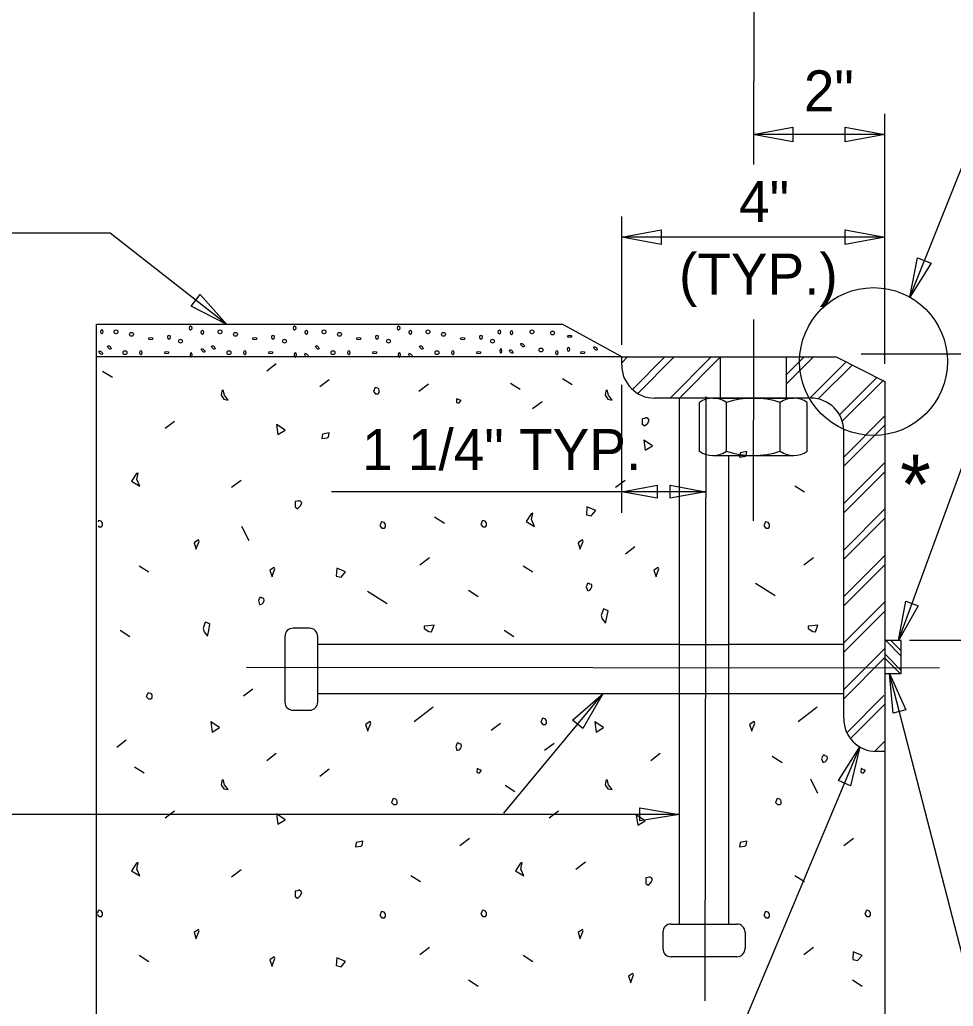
# Model space of a CAD drawing. Extents: x 0 to 11.3, y 0 to 7.9.
# Drawn here: x 1.652 to 2.835, y 1.767 to 3.018 of the extents above; entities that cross this region are included whole.
import ezdxf

# ---------------------------------------------------------------- set-up
doc = ezdxf.new("R2010")
doc.units = 0
for name, color, linetype in [('BRDG_ANNO_General-Notes', 7, 'Continuous'), ('BRDG_BASE_Dtlctrln', 7, 'Continuous'), ('BRDG_BASE_Hidden-Line', 7, 'Continuous'), ('BRDG_BASE_Obj-Line', 7, 'Continuous'), ('BRDG_BASE_Pattern', 7, 'Continuous')]:
    doc.layers.add(name, color=color, linetype=linetype)

msp = doc.modelspace()

# ---------------------------------------------------------------- linework, layer by layer
at = {"layer": 'BRDG_ANNO_General-Notes'}
for p, q in [((2.78, 2.6662), (2.9177, 3.0101)), ((2.7484, 2.5817), (2.7484, 2.8984)), ((2.5817, 2.8724), (2.6317, 2.8818)), ((2.6317, 2.8818), (2.6317, 2.863)), ((2.6984, 2.863), (2.6984, 2.8818)), ((2.6984, 2.8818), (2.7484, 2.8724)), ((2.7484, 2.8724), (2.5817, 2.8724)), ((2.6317, 2.863), (2.5817, 2.8724)), ((2.7484, 2.8724), (2.6984, 2.863)), ((2.4151, 2.6059), (2.4151, 2.7682)), ((2.4151, 2.7422), (2.4651, 2.7516)), ((2.4651, 2.7516), (2.4651, 2.7328)), ((2.6984, 2.7328), (2.6984, 2.7516)), ((2.6984, 2.7516), (2.7484, 2.7422)), ((1.7666, 2.7472), (0.6362, 2.7472)), ((1.9143, 2.6315), (1.7666, 2.7472)), ((2.7484, 2.7422), (2.4151, 2.7422)), ((2.4651, 2.7328), (2.4151, 2.7422)), ((2.7484, 2.7422), (2.6984, 2.7328)), ((2.78, 2.6662), (2.7899, 2.7161)), ((2.7899, 2.7161), (2.8073, 2.7091)), ((2.8073, 2.7091), (2.78, 2.6662)), ((1.8692, 2.6549), (1.8807, 2.6697)), ((1.8807, 2.6697), (1.9143, 2.6315)), ((1.9143, 2.6315), (1.8692, 2.6549)), ((2.8736, 2.5938), (2.7186, 2.5938)), ((2.7656, 2.2309), (2.8942, 2.5818)), ((2.4151, 2.3926), (2.4151, 2.5549)), ((2.4151, 2.4195), (2.4601, 2.4279)), ((2.4601, 2.4279), (2.4601, 2.4112)), ((2.4762, 2.4112), (2.4762, 2.4279)), ((2.4762, 2.4279), (2.5212, 2.4195)), ((2.4151, 2.4195), (2.0472, 2.4195)), ((2.5212, 2.4195), (2.4151, 2.4195)), ((2.4601, 2.4112), (2.4151, 2.4195)), ((2.5212, 2.4195), (2.4762, 2.4112)), ((2.5192, 2.4195), (2.5214, 2.4195)), ((2.7656, 2.2309), (2.7749, 2.2807)), ((2.7749, 2.2807), (2.7906, 2.2749)), ((2.7906, 2.2749), (2.7656, 2.2309)), ((2.905, 2.2309), (2.7798, 2.2309)), ((2.8534, 1.8065), (2.7544, 2.1892)), ((2.7589, 2.1387), (2.7544, 2.1892)), ((2.7544, 2.1892), (2.7749, 2.1429)), ((2.2654, 2.0119), (2.3911, 2.1632)), ((2.3528, 2.1301), (2.3911, 2.1632)), ((2.3911, 2.1632), (2.3656, 2.1194)), ((2.7749, 2.1429), (2.7589, 2.1387)), ((2.3656, 2.1194), (2.3528, 2.1301)), ((2.558, 1.7178), (2.7167, 2.0961)), ((2.6896, 2.0533), (2.7167, 2.0961)), ((2.7167, 2.0961), (2.705, 2.0468)), ((2.705, 2.0468), (2.6896, 2.0533)), ((2.438, 2.0021), (2.438, 2.0188)), ((2.438, 2.0188), (2.488, 2.0105)), ((2.488, 2.0105), (0.6091, 2.0105)), ((2.488, 2.0105), (2.438, 2.0021))]:
    msp.add_line(p, q, dxfattribs=at)
msp.add_circle((2.7341, 2.5845), 0.0937, dxfattribs=at)
at = {"layer": 'BRDG_BASE_Dtlctrln'}
for p, q in [((2.5838, 4.2478), (2.5821, 2.8344)), ((2.5819, 2.6378), (2.5816, 2.3826)), ((2.5214, 2.5404), (2.5204, 1.7741)), ((1.9392, 2.1972), (2.8176, 2.1961))]:
    msp.add_line(p, q, dxfattribs=at)
at = {"layer": 'BRDG_BASE_Hidden-Line'}
for p, q in [((2.488, 2.2257), (2.5505, 2.2257)), ((2.5505, 2.1632), (2.488, 2.1632))]:
    msp.add_line(p, q, dxfattribs=at)
at = {"layer": 'BRDG_BASE_Obj-Line'}
for p, q in [((2.3403, 2.6315), (1.7493, 2.6315)), ((1.7493, 2.5903), (1.7493, 2.6315)), ((2.4151, 2.5903), (2.3403, 2.6315)), ((2.4151, 2.5903), (1.7493, 2.5903)), ((1.7493, 1.6864), (1.7493, 2.5903)), ((2.4151, 2.5903), (2.6867, 2.5903)), ((2.4151, 2.5798), (2.4151, 2.5903)), ((2.6867, 2.5903), (2.7484, 2.5594)), ((2.7484, 2.5594), (2.7484, 2.0903)), ((2.6546, 2.5382), (2.4567, 2.5382)), ((2.488, 2.5382), (2.488, 1.8715)), ((2.5134, 2.4707), (2.5134, 2.5328)), ((2.5192, 2.5382), (2.5192, 2.5382)), ((2.6338, 2.5382), (2.5296, 2.5382)), ((2.5309, 2.5382), (2.5818, 2.5382)), ((2.5476, 2.4707), (2.5476, 2.5328)), ((2.5818, 2.5382), (2.6327, 2.5382)), ((2.6159, 2.4707), (2.6159, 2.5328)), ((2.6502, 2.4707), (2.6502, 2.5328)), ((2.6963, 2.1319), (2.6963, 2.4965)), ((2.5309, 2.4653), (2.5818, 2.4653)), ((2.5505, 2.4653), (2.5505, 1.8715)), ((2.5818, 2.4653), (2.6327, 2.4653)), ((2.0192, 2.2465), (1.9984, 2.2465)), ((1.988, 2.2361), (1.988, 2.1528)), ((2.0296, 2.2257), (2.0296, 2.2361)), ((2.0296, 2.1528), (2.0296, 2.2257)), ((2.488, 2.2257), (2.0296, 2.2257)), ((2.6963, 2.2257), (2.5505, 2.2257)), ((2.6963, 2.1944), (2.6963, 2.1944)), ((2.488, 2.1632), (2.0296, 2.1632)), ((2.6963, 2.1632), (2.5505, 2.1632)), ((2.0192, 2.1423), (1.9984, 2.1423)), ((2.7484, 2.0903), (2.738, 2.0903)), ((2.7484, 2.0903), (2.7484, 1.3157)), ((2.4776, 1.8715), (2.5505, 1.8715)), ((2.5505, 1.8715), (2.5609, 1.8715)), ((2.4671, 1.8611), (2.4671, 1.8403)), ((2.5713, 1.8611), (2.5713, 1.8403)), ((2.5609, 1.8298), (2.4776, 1.8298))]:
    msp.add_line(p, q, dxfattribs=at)
for points in [[(2.5402, 2.5903), (2.6234, 2.5903), (2.6234, 2.5382), (2.5402, 2.5382)], [(2.7484, 2.2309), (2.7484, 2.1892), (2.7692, 2.1892), (2.7692, 2.2309)]]:
    msp.add_lwpolyline(points, close=True, dxfattribs=at)
for centre, radius, start, end in [((2.4567, 2.5798), 0.0417, 180, 270), ((2.5305, 2.5086), 0.0296, 54.7697, 125.2303), ((2.5818, 2.4278), 0.1104, 71.9685, 108.0316), ((2.633, 2.5086), 0.0296, 54.7697, 125.2303), ((2.6546, 2.4965), 0.0417, 0, 90), ((2.5305, 2.4949), 0.0296, 234.7697, 305.2303), ((2.5818, 2.5757), 0.1104, 251.9684, 288.0315), ((2.633, 2.4949), 0.0296, 234.7697, 305.2303), ((1.9984, 2.2361), 0.0104, 90, 180), ((2.0192, 2.2361), 0.0104, 0, 90), ((1.9984, 2.1528), 0.0104, 180, 270), ((2.0192, 2.1528), 0.0104, 270, 360), ((2.738, 2.1319), 0.0417, 180, 270), ((2.4776, 1.8611), 0.0104, 90, 180), ((2.5609, 1.8611), 0.0104, 0, 90), ((2.4776, 1.8403), 0.0104, 180, 270), ((2.5609, 1.8403), 0.0104, 270, 0)]:
    msp.add_arc(centre, radius, start, end, dxfattribs=at)
at = {"layer": 'BRDG_BASE_Pattern'}
for p, q in [((1.977, 2.5815), (1.965, 2.5724)), ((2.6532, 2.5382), (2.6985, 2.5835)), ((2.6639, 2.5371), (2.7069, 2.5801)), ((1.757, 2.5724), (1.7694, 2.5646)), ((2.6909, 2.517), (2.7378, 2.5639)), ((2.0443, 2.5615), (2.0322, 2.5523)), ((2.17, 2.5557), (2.158, 2.5466)), ((2.274, 2.5572), (2.2864, 2.5494)), ((2.3399, 2.5632), (2.3523, 2.5554)), ((2.3142, 2.5336), (2.3021, 2.5244)), ((1.8483, 2.5086), (1.8362, 2.4995)), ((1.9326, 2.4339), (1.9205, 2.4247)), ((2.4192, 2.4339), (2.4072, 2.4247)), ((2.6344, 2.4271), (2.6467, 2.4193)), ((2.1778, 2.3876), (2.1902, 2.3798)), ((1.9331, 2.3759), (1.9423, 2.3576)), ((2.4317, 2.3495), (2.4197, 2.3404)), ((2.1712, 2.3356), (2.1592, 2.3264)), ((2.6579, 2.3356), (2.6458, 2.3264)), ((1.8035, 2.3257), (1.8158, 2.318)), ((2.2902, 2.3257), (2.3025, 2.318)), ((2.5845, 2.3036), (2.6093, 2.288)), ((2.0928, 2.2935), (2.1175, 2.2779)), ((2.2208, 2.2946), (2.2332, 2.2868)), ((1.7793, 2.2439), (1.7917, 2.236)), ((2.266, 2.2439), (2.2783, 2.236)), ((1.9475, 2.1694), (1.9355, 2.1602)), ((2.1758, 2.1462), (2.1518, 2.1279)), ((2.6626, 2.1462), (2.6385, 2.1279)), ((2.2614, 2.1257), (2.2493, 2.1166)), ((1.7869, 2.1046), (1.7749, 2.0954)), ((2.3293, 2.1004), (2.3173, 2.0913)), ((1.977, 2.0877), (1.965, 2.0785)), ((2.4637, 2.0877), (2.4517, 2.0785)), ((2.6058, 2.0841), (2.6182, 2.0762)), ((1.7973, 2.0709), (1.8097, 2.0631)), ((2.0443, 2.0676), (2.0322, 2.0584)), ((2.6542, 2.0556), (2.6633, 2.0372)), ((2.2671, 2.0473), (2.2795, 2.0395)), ((1.8483, 2.0147), (1.8362, 2.0056)), ((2.3349, 2.0147), (2.3229, 2.0056)), ((2.2219, 1.9797), (2.2099, 1.9705)), ((2.7086, 1.9797), (2.6966, 1.9705)), ((1.9326, 1.94), (1.9205, 1.9308)), ((2.369, 1.9498), (2.357, 1.9406)), ((2.1477, 1.9332), (2.1601, 1.9254)), ((2.6344, 1.9332), (2.6467, 1.9254)), ((2.1712, 1.8417), (2.1592, 1.8325)), ((2.6579, 1.8417), (2.6458, 1.8325)), ((1.8035, 1.8318), (1.8158, 1.8241)), ((2.2902, 1.8318), (2.3025, 1.8241)), ((2.2208, 1.8007), (2.2332, 1.7929)), ((2.7074, 1.8007), (2.7198, 1.7929))]:
    msp.add_line(p, q, dxfattribs=at)
for points in [[(2.4151, 2.5829), (2.4224, 2.5903)], [(2.4285, 2.5492), (2.4695, 2.5903)], [(2.4352, 2.5441), (2.4813, 2.5903)], [(2.4764, 2.5382), (2.5285, 2.5903)], [(2.4882, 2.5382), (2.5395, 2.5895)], [(2.6231, 2.5553), (2.6581, 2.5903)], [(2.6232, 2.5671), (2.6463, 2.5903)], [(2.6944, 2.5088), (2.7468, 2.5611)], [(2.6963, 2.4634), (2.7484, 2.5156)], [(2.6963, 2.4517), (2.7484, 2.5038)], [(2.6963, 2.4045), (2.7484, 2.4566)], [(2.6963, 2.3928), (2.7484, 2.4448)], [(2.6963, 2.3456), (2.7484, 2.3977)], [(1.7513, 2.3761), (1.7524, 2.375), (1.7557, 2.375), (1.757, 2.3765), (1.757, 2.3792), (1.7566, 2.3805), (1.7552, 2.382), (1.752, 2.3829), (1.7513, 2.3814)], [(2.6963, 2.3338), (2.7484, 2.3859)], [(2.6963, 2.2867), (2.7484, 2.3388)], [(2.6963, 2.2749), (2.7484, 2.327)], [(2.6963, 2.2278), (2.7484, 2.2798)], [(2.6963, 2.216), (2.7484, 2.2681)], [(2.7692, 2.2112), (2.7496, 2.2309)], [(2.7692, 2.2178), (2.7561, 2.2309)], [(2.6963, 2.1688), (2.7484, 2.2209)], [(2.7692, 2.1929), (2.7484, 2.2138)], [(2.6963, 2.157), (2.7484, 2.2092)], [(2.7678, 2.1892), (2.7484, 2.2087)], [(2.7004, 2.114), (2.7473, 2.161)], [(2.7049, 2.1067), (2.7484, 2.1502)], [(2.7357, 2.0904), (2.7484, 2.1031)], [(1.7505, 2.0661), (1.7506, 2.0663), (1.7505, 2.0663)], [(1.7501, 1.8835), (1.7524, 1.8811), (1.7557, 1.8811), (1.757, 1.8826), (1.757, 1.8853), (1.7566, 1.8866), (1.7552, 1.8881), (1.752, 1.889), (1.7501, 1.8847)]]:
    msp.add_lwpolyline(points, dxfattribs=at)
for points in [[(2.1026, 2.5517), (2.1002, 2.5466), (2.1029, 2.5438), (2.1062, 2.5438), (2.1076, 2.5453), (2.1076, 2.548), (2.1071, 2.5493), (2.1057, 2.5508)], [(1.9081, 2.5471), (1.9071, 2.5419), (1.9106, 2.5368), (1.9163, 2.5357), (1.9117, 2.5418), (1.9097, 2.5481)], [(2.3948, 2.5471), (2.3938, 2.5419), (2.3972, 2.5368), (2.403, 2.5357), (2.3984, 2.5418), (2.3965, 2.5481)], [(2.2057, 2.5374), (2.2055, 2.5325), (2.2085, 2.5318), (2.2114, 2.5352)], [(1.9774, 2.5049), (1.9793, 2.4921), (1.9885, 2.4976)], [(2.4411, 2.5121), (2.4411, 2.5052), (2.4443, 2.5029), (2.4452, 2.5038), (2.4479, 2.5066), (2.4498, 2.5103), (2.4484, 2.5121), (2.4466, 2.513), (2.4457, 2.513), (2.4439, 2.5125)], [(2.0359, 2.4925), (2.035, 2.487), (2.0415, 2.4879), (2.0433, 2.4888), (2.0442, 2.4943)], [(2.443, 2.4849), (2.4448, 2.4721), (2.4541, 2.4776)], [(2.5652, 2.4686), (2.5643, 2.4631), (2.5707, 2.464), (2.5726, 2.4649), (2.5735, 2.4704)], [(1.7999, 2.4426), (1.7935, 2.4329), (1.8043, 2.4264), (1.8004, 2.4352), (1.802, 2.4432)], [(2.0011, 2.4072), (2.0011, 2.4003), (2.0042, 2.398), (2.0052, 2.3989), (2.0079, 2.4017), (2.0097, 2.4054), (2.0084, 2.4072), (2.0066, 2.4081), (2.0057, 2.4081), (2.0039, 2.4076)], [(2.3002, 2.3916), (2.2937, 2.3819), (2.3045, 2.3755), (2.3006, 2.3842), (2.3022, 2.3922)], [(2.3707, 2.4002), (2.3703, 2.3903), (2.3762, 2.3889), (2.382, 2.3956)], [(2.1106, 2.3813), (2.1083, 2.3762), (2.111, 2.3734), (2.1143, 2.3734), (2.1157, 2.3748), (2.1157, 2.3776), (2.1152, 2.3789), (2.1138, 2.3804)], [(2.2387, 2.3829), (2.2364, 2.3778), (2.2391, 2.375), (2.2424, 2.375), (2.2437, 2.3765), (2.2437, 2.3792), (2.2433, 2.3805), (2.2418, 2.382)], [(2.5973, 2.3813), (2.595, 2.3762), (2.5977, 2.3734), (2.601, 2.3734), (2.6024, 2.3748), (2.6024, 2.3776), (2.6019, 2.3789), (2.6005, 2.3804)], [(1.873, 2.3548), (1.8758, 2.3465), (1.8758, 2.3474), (1.8795, 2.3566), (1.8785, 2.3585)], [(2.3596, 2.3548), (2.3625, 2.3465), (2.3625, 2.3474), (2.3662, 2.3566), (2.3653, 2.3585)], [(1.969, 2.32), (1.9718, 2.3117), (1.9718, 2.3126), (1.9755, 2.3218), (1.9746, 2.3236)], [(2.0537, 2.3225), (2.0532, 2.3126), (2.0592, 2.3112), (2.0649, 2.3179)], [(2.4557, 2.32), (2.4585, 2.3117), (2.4585, 2.3126), (2.4622, 2.3218), (2.4612, 2.3236)], [(2.37, 2.299), (2.3715, 2.2944), (2.3728, 2.2944), (2.3746, 2.2948), (2.376, 2.2962), (2.3773, 2.299), (2.377, 2.3018), (2.3746, 2.3022), (2.3737, 2.3032), (2.3718, 2.3032)], [(1.9545, 2.2814), (1.956, 2.2767), (1.9573, 2.2767), (1.9592, 2.2772), (1.9606, 2.2785), (1.9619, 2.2814), (1.9615, 2.2841), (1.9592, 2.2846), (1.9582, 2.2855), (1.9564, 2.2855)], [(2.3917, 2.271), (2.3889, 2.2627), (2.3903, 2.2585), (2.3944, 2.253), (2.3962, 2.2604), (2.3977, 2.2687)], [(1.8871, 2.2543), (1.8844, 2.2459), (1.8858, 2.2418), (1.8899, 2.2363), (1.8917, 2.2436), (1.8931, 2.252)], [(2.1701, 2.2495), (2.1646, 2.2491), (2.1646, 2.2463), (2.1706, 2.2422), (2.1739, 2.2417), (2.1771, 2.2504)], [(2.6568, 2.2495), (2.6513, 2.2491), (2.6513, 2.2463), (2.6573, 2.2422), (2.6605, 2.2417), (2.6637, 2.2504)], [(1.8147, 2.1647), (1.8123, 2.1597), (1.8151, 2.1569), (1.8184, 2.1569), (1.8197, 2.1583), (1.8197, 2.161), (1.8193, 2.1623), (1.8179, 2.1639)], [(1.8941, 2.1279), (1.896, 2.1149), (1.9052, 2.1205)], [(2.0904, 2.1244), (2.0932, 2.1161), (2.0932, 2.117), (2.0969, 2.1262), (2.096, 2.1281)], [(2.3147, 2.1324), (2.3124, 2.1274), (2.3151, 2.1246), (2.3184, 2.1246), (2.3198, 2.126), (2.3198, 2.1288), (2.3193, 2.1301), (2.3179, 2.1316)], [(2.3808, 2.1279), (2.3827, 2.1149), (2.3919, 2.1205)], [(2.5771, 2.1244), (2.5799, 2.1161), (2.5799, 2.117), (2.5836, 2.1262), (2.5827, 2.1281)], [(2.2046, 2.0966), (2.2061, 2.092), (2.2074, 2.092), (2.2093, 2.0925), (2.2107, 2.0938), (2.212, 2.0966), (2.2116, 2.0994), (2.2093, 2.0998), (2.2083, 2.1008), (2.2065, 2.1008)], [(2.6683, 2.0812), (2.6698, 2.0767), (2.6711, 2.0767), (2.673, 2.0771), (2.6743, 2.0784), (2.6757, 2.0812), (2.6753, 2.084), (2.673, 2.0845), (2.672, 2.0854), (2.6702, 2.0854)], [(2.2317, 2.0685), (2.2315, 2.0636), (2.2345, 2.0629), (2.2373, 2.0663)], [(2.7184, 2.0685), (2.7182, 2.0636), (2.7211, 2.0629), (2.724, 2.0663)], [(1.9081, 2.0532), (1.9071, 2.048), (1.9106, 2.0429), (1.9163, 2.0418), (1.9117, 2.0479), (1.9097, 2.0542)], [(2.3948, 2.0532), (2.3938, 2.048), (2.3972, 2.0429), (2.403, 2.0418), (2.3984, 2.0479), (2.3965, 2.0542)], [(2.1254, 2.0307), (2.1231, 2.0257), (2.1258, 2.0229), (2.1291, 2.0229), (2.1305, 2.0243), (2.1305, 2.027), (2.13, 2.0283), (2.1285, 2.0298)], [(2.6121, 2.0307), (2.6098, 2.0257), (2.6125, 2.0229), (2.6158, 2.0229), (2.6171, 2.0243), (2.6171, 2.027), (2.6167, 2.0283), (2.6153, 2.0298)], [(1.9774, 2.0111), (1.9793, 1.9982), (1.9885, 2.0037)], [(2.4334, 2.0097), (2.4353, 1.9968), (2.4446, 2.0023)], [(2.0785, 1.9747), (2.0776, 1.9692), (2.0841, 1.9701), (2.0859, 1.971), (2.0868, 1.9766)], [(2.5652, 1.9747), (2.5643, 1.9692), (2.5707, 1.9701), (2.5726, 1.971), (2.5735, 1.9766)], [(1.7999, 1.9486), (1.7935, 1.939), (1.8043, 1.9325), (1.8004, 1.9412), (1.802, 1.9493)], [(2.2866, 1.9486), (2.2802, 1.939), (2.291, 1.9325), (2.287, 1.9412), (2.2887, 1.9493)], [(2.4455, 1.93), (2.4455, 1.923), (2.4486, 1.9208), (2.4496, 1.9217), (2.4523, 1.9244), (2.4542, 1.9281), (2.4528, 1.93), (2.451, 1.9309), (2.4501, 1.9309), (2.4483, 1.9304)], [(2.0011, 1.9133), (2.0011, 1.9064), (2.0042, 1.9041), (2.0052, 1.905), (2.0079, 1.9078), (2.0097, 1.9115), (2.0084, 1.9133), (2.0066, 1.9142), (2.0057, 1.9142), (2.0039, 1.9137)], [(2.2387, 1.889), (2.2364, 1.8839), (2.2391, 1.8811), (2.2424, 1.8811), (2.2437, 1.8826), (2.2437, 1.8853), (2.2433, 1.8866), (2.2418, 1.8881)], [(2.7254, 1.889), (2.7231, 1.8839), (2.7258, 1.8811), (2.7291, 1.8811), (2.7304, 1.8826), (2.7304, 1.8853), (2.7299, 1.8866), (2.7285, 1.8881)], [(2.1106, 1.8873), (2.1083, 1.8823), (2.111, 1.8795), (2.1143, 1.8795), (2.1157, 1.8809), (2.1157, 1.8836), (2.1152, 1.885), (2.1138, 1.8865)], [(2.5973, 1.8873), (2.595, 1.8823), (2.5977, 1.8795), (2.601, 1.8795), (2.6024, 1.8809), (2.6024, 1.8836), (2.6019, 1.885), (2.6005, 1.8865)], [(1.873, 1.8609), (1.8758, 1.8526), (1.8758, 1.8535), (1.8795, 1.8628), (1.8785, 1.8646)], [(2.3596, 1.8609), (2.3625, 1.8526), (2.3625, 1.8535), (2.3662, 1.8628), (2.3653, 1.8646)], [(1.969, 1.8261), (1.9718, 1.8178), (1.9718, 1.8187), (1.9755, 1.8279), (1.9746, 1.8298)], [(2.0537, 1.8286), (2.0532, 1.8187), (2.0592, 1.8173), (2.0649, 1.824)], [(2.7083, 1.8364), (2.7079, 1.8265), (2.7139, 1.8251), (2.7196, 1.8317)], [(2.4236, 1.8052), (2.4265, 1.7969), (2.4265, 1.7978), (2.4301, 1.807), (2.4292, 1.8089)]]:
    msp.add_lwpolyline(points, close=True, dxfattribs=at)
for centre in [(1.774, 2.6222), (1.7937, 2.619), (1.9058, 2.6222), (1.9255, 2.619), (2.0376, 2.6222), (2.0573, 2.619), (2.1694, 2.6222), (2.1891, 2.619), (2.3012, 2.6222), (2.3272, 2.6208), (1.8557, 2.6104), (1.9875, 2.6104), (2.1193, 2.6104), (2.2512, 2.6104), (2.3127, 2.5992), (1.7854, 2.5958), (1.9172, 2.5958), (2.049, 2.5958), (2.1808, 2.5958)]:
    msp.add_circle(centre, 0.00244, dxfattribs=at)
for centre, major_axis in [((1.8686, 2.627), (0, -0.00275)), ((2.0004, 2.627), (0, -0.00275)), ((2.1322, 2.627), (0, -0.00275)), ((1.756, 2.6223), (0, -0.00275)), ((1.8178, 2.6135), (-0.00275, 0)), ((1.8412, 2.6154), (0, -0.00275)), ((1.8835, 2.6215), (0, -0.00275)), ((1.9496, 2.6135), (-0.00275, 0)), ((1.973, 2.6154), (0, -0.00275)), ((2.0153, 2.6215), (0, -0.00275)), ((2.0814, 2.6135), (-0.00275, 0)), ((2.1049, 2.6154), (0, -0.00275)), ((2.1471, 2.6215), (0, -0.00275)), ((2.2132, 2.6135), (-0.00275, 0)), ((2.2367, 2.6154), (0, -0.00275)), ((2.2599, 2.622), (0, -0.00275)), ((2.2753, 2.6213), (0, -0.00275)), ((2.349, 2.6166), (-0.00275, 0)), ((1.7656, 2.6023), (0.00195, -0.00195)), ((1.8974, 2.6023), (0.00195, -0.00195)), ((2.0292, 2.6023), (0.00195, -0.00195)), ((2.1611, 2.6023), (0.00195, -0.00195)), ((2.2892, 2.6054), (0.00195, -0.00195)), ((2.3476, 2.5999), (0, -0.00275)), ((2.3818, 2.6012), (0.00195, -0.00195)), ((1.7546, 2.5958), (0.00195, -0.00195)), ((1.8055, 2.5958), (0, -0.00275)), ((1.8382, 2.5957), (-0.00275, 0)), ((1.8845, 2.5986), (0.00195, -0.00195)), ((1.9373, 2.5958), (0, -0.00275)), ((1.97, 2.5957), (-0.00275, 0)), ((2.0153, 2.5925), (0.00195, -0.00195)), ((2.0691, 2.5958), (0, -0.00275)), ((2.1019, 2.5957), (-0.00275, 0)), ((2.1471, 2.5925), (0.00195, -0.00195)), ((2.2009, 2.5958), (0, -0.00275)), ((2.2337, 2.5957), (-0.00275, 0)), ((2.275, 2.5973), (0.00195, -0.00195)), ((2.3327, 2.5958), (0, -0.00275)), ((2.3655, 2.5957), (-0.00275, 0))]:
    msp.add_ellipse(centre, major_axis=major_axis, ratio=0.5, dxfattribs=at)
for centre in [(1.8693, 2.593), (2.0012, 2.593), (2.133, 2.593), (2.2617, 2.5981)]:
    msp.add_ellipse(centre, major_axis=(0, -0.00275), ratio=0.5, start_param=0.00615, end_param=6.277035, dxfattribs=at)

# ---------------------------------------------------------------- texts
at = {"layer": 'BRDG_ANNO_General-Notes'}
for s, height, p in [('2"', 0.05208, (2.6458, 2.9016)), ('4"', 0.05208, (2.5637, 2.7615)), ('(TYP.)', 0.05208, (2.4876, 2.6694)), ('1 1/4" TYP.', 0.052083, (2.0859, 2.4469)), ('*', 0.0751, (2.7678, 2.3913))]:
    msp.add_text(s, height=height, dxfattribs=at).set_placement(p)

doc.saveas('drawing.dxf')
